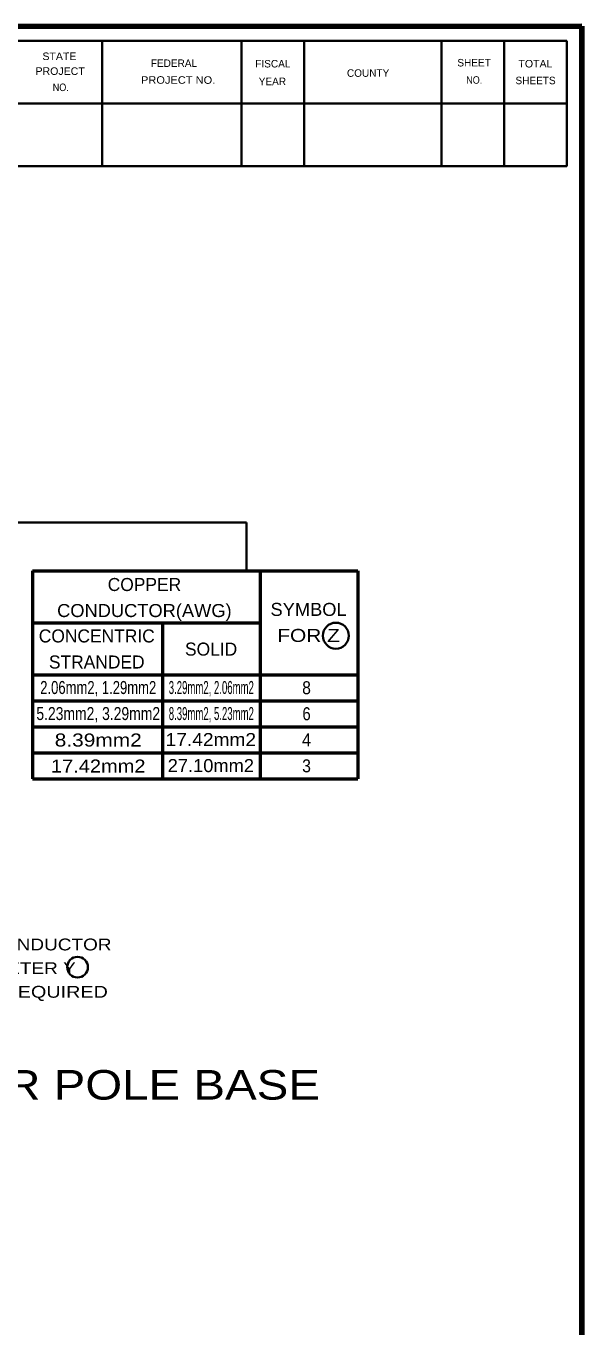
# Model space of a CAD drawing. Extents: x -32 to 824, y -6 to 538.
# Drawn here: x 704.6 to 817.4, y 267.9 to 531.7 of the extents above; entities that cross this region are included whole.
import ezdxf
from ezdxf.enums import TextEntityAlignment as Align

# ---------------------------------------------------------------- set-up
doc = ezdxf.new("R2010")
doc.units = 0
doc.header["$LTSCALE"] = 1.1
doc.layers.add('1', color=7, linetype='Continuous', lineweight=53)
doc.layers.add('61', color=7, linetype='Continuous', lineweight=35)

msp = doc.modelspace()

# ---------------------------------------------------------------- linework, layer by layer
at = {"layer": '1', "lineweight": 158}
msp.add_line((817.398, 5.644), (817.398, 531.744), dxfattribs=at)
at = {"layer": '1', "lineweight": 13}
msp.add_line((817.398, 5.644), (817.398, 531.744), dxfattribs=at)
at = {"layer": '1', "lineweight": 35}
for p, q in [((644.536, 431.073), (749.283, 431.073)), ((749.283, 431.073), (749.283, 421.473))]:
    msp.add_line(p, q, dxfattribs=at)
at = {"layer": '1'}
for p, q in [((705.889, 421.292), (705.889, 379.052)), ((705.889, 421.292), (771.889, 421.292)), ((752.089, 421.292), (752.089, 379.052)), ((771.889, 421.292), (771.889, 379.052)), ((705.889, 410.732), (752.089, 410.732)), ((732.289, 410.732), (732.289, 379.052)), ((705.889, 400.172), (771.889, 400.172)), ((705.889, 394.892), (771.889, 394.892)), ((705.889, 389.612), (771.889, 389.612)), ((705.889, 384.332), (771.889, 384.332)), ((705.889, 379.052), (771.889, 379.052))]:
    msp.add_line(p, q, dxfattribs=at)
at = {"layer": '1', "lineweight": 158}
msp.add_lwpolyline([(817.398, 531.744), (25.698, 531.644), (25.798, 5.644)], dxfattribs=at)
at = {"layer": '1', "lineweight": 35}
for centre, radius in [((767.451, 408.111), 2.64), ((715.029, 340.898), 2.1)]:
    msp.add_circle(centre, radius, dxfattribs=at)
at = {"layer": '61'}
for p, q in [((719.998, 528.744), (719.998, 503.344)), ((748.298, 528.744), (748.298, 503.344)), ((760.998, 528.744), (760.998, 503.344)), ((788.898, 528.744), (788.898, 503.344)), ((801.598, 528.744), (801.598, 503.344)), ((814.298, 516.044), (677.198, 516.044))]:
    msp.add_line(p, q, dxfattribs=at)
for points in [[(814.298, 528.744), (677.198, 528.744), (677.198, 503.344)], [(814.298, 528.744), (814.298, 503.344), (677.198, 503.344)]]:
    msp.add_lwpolyline(points, dxfattribs=at)

# ---------------------------------------------------------------- texts
at = {"layer": '1'}
for s, p in [('COPPER', (728.602, 417.172)), ('CONCENTRIC', (718.929, 406.739)), ('STRANDED', (718.929, 401.459))]:
    msp.add_text(s, height=2.64, dxfattribs=at).set_placement(p, align=Align.CENTER)
for s, height, width, p in [('CONDUCTOR(AWG)', 2.64, 1.05, (728.592, 411.892)), ('SYMBOL', 2.64, 1.05, (761.91, 412.124)), ('FOR Z', 2.64, 1.2, (761.91, 406.844)), ('2.06mm2, 1.29mm2', 2.64, 0.75, (719.227, 396.284)), ('3.29mm2, 2.06mm2', 2.64, 0.55, (742.176, 396.284)), ('8', 2.64, 0.9, (761.5, 396.242)), ('5.23mm2, 3.29mm2', 2.64, 0.8, (719.227, 391.004)), ('8.39mm2, 5.23mm2', 2.64, 0.55, (742.177, 391.004)), ('6', 2.64, 0.85, (761.5, 390.962)), ('8.39mm2', 2.64, 1.2, (719.227, 385.637)), ('17.42mm2', 2.64, 1.1, (742.079, 385.735)), ('4', 2.64, 0.95, (761.5, 385.682)), ('17.42mm2', 2.64, 1.15, (719.227, 380.357)), ('27.10mm2', 2.64, 1.05, (742.079, 380.455)), ('3', 2.64, 0.9, (761.5, 380.402)), ('UNFUSED "Y" CONNECTOR KIT FOR POLE BASE', 6, 1.2, (651.939, 314.034))]:
    msp.add_text(s, height=height, dxfattribs=dict(at, width=width)).set_placement(p, align=Align.CENTER)
msp.add_text('SOLID', height=2.64, dxfattribs=at).set_placement((736.835, 404.073))
for s, width, p in [('IF THE LINE SIDE CABLE OUTSIDE DIAMETER W IS 13.7mm AND THE CONDUCTOR', 1.2, (568.716, 344.295)), ('X IS 43.23mm2 STRANDED, AND THE LOAD SIDE CABLE OUTSIDE DIAMETER Y', 1.2, (568.716, 339.495)), ('IS 7.4mm AND THE CONDUCTOR Z IS 3.29mm2 STRANDED, THE KIT REQUIRED', 1.25, (568.716, 334.695))]:
    msp.add_text(s, height=2.4, dxfattribs=dict(at, width=width)).set_placement(p)
at = {"layer": '61'}
for s, rotation, width, p in [('STATE', 0.059, 1.05, (707.898, 524.844)), ('PROJECT', 359.908, 1.05, (706.498, 521.844)), ('TOTAL', 359.926, 1.05, (804.498, 523.344)), ('NO.', 0.225, 0.9, (709.998, 518.544)), ('PROJECT NO.', 359.922, 1.1, (727.898, 520.044)), ('NO.', 359.852, 0.9, (793.898, 520.044))]:
    msp.add_text(s, height=1.525, rotation=rotation, dxfattribs=dict(at, width=width)).set_placement(p)
for s, height, rotation, p in [('SHEET', 1.525, 0.059, (792.098, 523.544)), ('FEDERAL', 1.523, 0.007, (729.898, 523.444)), ('FISCAL', 1.525, 359.942, (751.098, 523.344)), ('COUNTY', 1.523, 0.069, (769.698, 521.444)), ('YEAR', 1.523, 0.105, (751.798, 519.744)), ('SHEETS', 1.523, 359.959, (803.898, 519.944))]:
    msp.add_text(s, height=height, rotation=rotation, dxfattribs=at).set_placement(p)

doc.saveas('drawing.dxf')
